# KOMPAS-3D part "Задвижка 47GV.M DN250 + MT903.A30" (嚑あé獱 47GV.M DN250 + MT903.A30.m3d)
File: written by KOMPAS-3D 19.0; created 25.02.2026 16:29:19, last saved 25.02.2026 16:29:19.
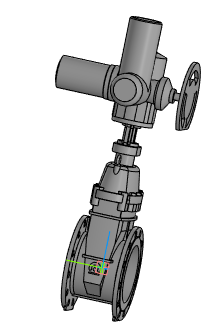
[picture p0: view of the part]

Document properties: Автор: Евгений; Полное имя файла: ..\..\47GVM\DR.47GVM.250.16.00.000\DR.47GVM.250.16.00.00 - Задвижка с обрезиненным клином DN250.a3d

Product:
- Part/product: Задвижка 47GV.M DN250 + MT903.A30
    Масса: 327.515
  - Component: Задвижка с обрезиненным клином DN250. Сборочный чертеж  | designation DR.47GVM.250.16.00.00СБ  | pos. 0  | Масса: 79.6129; Раздел спецификации: Документация; Форматы листов документа: 2xA3; source file: 47GV.M DN250\DR.47GVM.250.16.00.000 СБ - Задвижка с обрезиненным клином DN250.cdw

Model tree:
1. Операция без истории:1

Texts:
  Точка начала. Х
  Точка начала. Y
  Точка начала. Z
